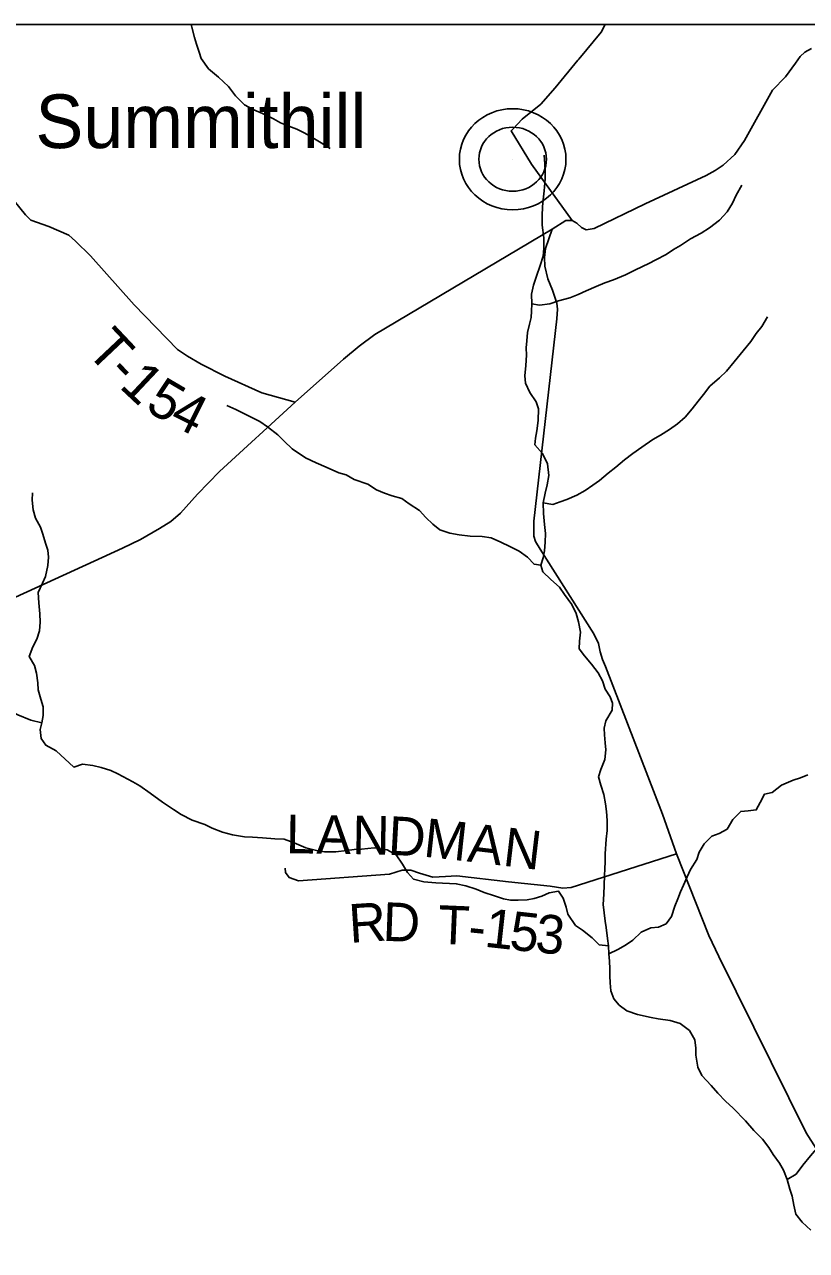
# Model space of a CAD drawing. Extents: x -139 to 835, y 0 to 440.
# Drawn here: x 206.1 to 242.7, y 344.1 to 401.5 of the extents above; entities that cross this region are included whole.
import ezdxf

# ---------------------------------------------------------------- set-up
doc = ezdxf.new("R2010")
doc.units = 0
for name, color, linetype in [('GM_X_County_Road', 7, 'Continuous'), ('GM_X_County_Text', 7, 'Continuous'), ('GM_X_Minor_River', 7, 'Continuous'), ('GM_X_State_Route', 7, 'Continuous'), ('GM_X_Township_Road', 7, 'Continuous'), ('GM_X_Township_Road_Text', 7, 'Continuous'), ('GM_X_Unincorporated', 7, 'Continuous'), ('GM_X_Unincorporated_Location', 7, 'Continuous'), ('GM_X_Unincorporated_Text', 7, 'Continuous'), ('SH_Cut_Line', 7, 'Continuous')]:
    doc.layers.add(name, color=color, linetype=linetype)

msp = doc.modelspace()

# ---------------------------------------------------------------- linework, layer by layer
at = {"layer": 'GM_X_County_Road'}
msp.add_lwpolyline([(243.129, 348.918), (242.661, 349.639), (238.58, 357.897), (238.118, 358.871), (236.599, 362.688), (235.94, 364.547), (233.28, 371.463), (233.147, 371.78), (233.028, 372.144), (232.948, 372.532), (232.741, 372.982), (230.219, 376.952), (230.011, 377.306), (229.927, 377.549), (229.93, 378.249), (231.007, 387.712), (231.043, 388.169), (230.999, 388.46), (230.795, 389.055), (230.578, 389.59), (230.439, 390.184), (230.435, 390.594), (230.47, 391.004), (230.781, 391.915)], dxfattribs=at)
at = {"layer": 'GM_X_County_Text'}
msp.add_lwpolyline([(295.458, 319.381), (295.458, 401.486), (205.139, 401.486), (203.623, 399.152), (203.278, 397.973), (203.246, 397.371), (203.294, 397.153), (203.078, 396.689), (187.014, 361.689), (186.616, 361.275), (186.292, 360.95), (186.018, 360.334), (185.902, 359.821), (185.729, 359.048), (185.383, 358.364), (184.767, 357.384), (172.321, 330.669), (171.559, 329.033), (177.155, 328.576), (194.287, 327.176), (207.436, 326.102), (228.151, 324.569), (267.909, 321.538)], close=True, dxfattribs=at)
at = {"layer": 'GM_X_Minor_River'}
for points in [[(213.904, 401.486), (213.938, 401.357), (214.06, 400.886), (214.157, 400.56), (214.268, 400.197), (214.366, 399.895), (214.704, 399.421), (215.182, 399.019), (215.647, 398.58), (215.973, 398.155), (216.4, 397.729), (216.83, 397.496), (217.234, 397.323), (217.753, 397.077), (218.081, 396.893), (218.473, 396.732), (218.84, 396.584), (219.219, 396.411), (219.598, 396.191), (219.977, 395.946), (220.406, 395.688)], [(230.406, 395.372), (230.44, 394.974), (230.461, 394.588), (230.457, 394.263), (230.412, 393.709), (230.369, 393.287), (230.34, 392.962), (230.323, 392.54), (230.317, 392.107), (230.4, 391.515), (230.394, 391.009), (230.364, 390.648), (230.232, 390.215), (230.061, 389.711), (229.916, 389.29), (229.822, 388.881), (229.83, 388.423), (229.826, 388.086), (229.797, 387.785), (229.73, 387.472), (229.636, 387.087), (229.594, 386.69), (229.577, 386.365), (229.586, 386.015), (229.555, 385.533), (229.511, 385.052), (229.545, 384.714), (229.744, 384.278), (230.044, 383.841), (230.154, 383.515), (230.135, 382.96), (230.066, 382.479), (230.011, 382.13), (229.982, 381.829), (230.334, 381.428), (230.569, 380.931), (230.627, 380.388), (230.558, 379.955), (230.465, 379.57), (230.37, 379.113), (230.377, 378.607), (230.435, 378.1), (230.468, 377.678), (230.463, 377.268), (230.421, 376.871), (230.366, 376.534), (230.26, 376.198), (230.346, 375.883), (230.723, 375.53), (231.125, 375.165), (231.363, 374.825), (231.713, 374.351), (231.912, 373.939), (232.022, 373.541), (232.118, 373.07), (232.062, 372.648), (232.045, 372.287), (232.296, 371.959), (232.622, 371.57), (232.935, 371.157), (233.147, 370.794), (233.269, 370.395), (233.494, 370.043), (233.605, 369.74), (233.588, 369.415), (233.29, 368.912), (233.223, 368.575), (233.232, 368.262), (233.266, 367.888), (233.3, 367.562), (233.257, 367.105), (233.06, 366.637), (232.955, 366.3), (233.065, 365.913), (233.2, 365.466), (233.284, 365.031), (233.33, 364.669), (233.364, 364.259), (233.358, 363.789), (233.315, 363.38), (233.269, 362.694), (233.265, 362.32), (233.248, 361.995), (233.232, 361.682), (233.214, 361.236), (233.197, 360.814), (233.178, 360.332), (233.212, 359.934), (233.271, 359.548), (233.318, 359.246), (233.376, 358.74), (233.423, 358.39), (233.444, 358.016), (233.465, 357.678), (233.487, 357.317), (233.483, 356.991), (233.492, 356.666), (233.538, 356.292), (233.674, 355.917), (233.925, 355.613), (234.278, 355.356)], [(229.83, 388.423), (230.198, 388.359), (230.682, 388.427), (231.09, 388.567), (231.613, 388.695), (232.009, 388.86), (232.379, 389.025), (232.852, 389.237), (233.248, 389.402), (233.656, 389.542), (234.218, 389.778), (234.691, 390.014), (235.305, 390.309), (235.637, 390.475), (236.111, 390.723), (236.456, 390.961), (236.789, 391.15), (237.263, 391.459), (237.762, 391.731), (238.146, 391.981), (238.621, 392.338), (238.969, 392.732), (239.215, 393.127), (239.397, 393.499), (239.657, 393.978)], [(230.37, 379.113), (230.814, 379.036), (231.159, 379.154), (231.478, 379.271), (231.938, 379.471), (232.335, 379.696), (232.681, 379.934), (233.001, 380.16), (233.412, 380.493), (233.758, 380.779), (234.169, 381.124), (234.566, 381.422), (234.977, 381.719), (235.502, 382.075), (235.86, 382.277), (236.27, 382.538), (236.642, 382.811), (237.001, 383.121), (237.336, 383.503), (237.62, 383.862), (237.865, 384.173), (238.162, 384.568), (238.611, 384.961), (238.933, 385.271), (239.294, 385.702), (239.719, 386.216), (240.08, 386.658), (240.326, 387.041), (240.597, 387.364), (240.856, 387.808)], [(230.26, 376.198), (229.943, 376.237), (229.629, 376.565), (229.238, 376.846), (228.809, 377.068), (228.379, 377.277), (227.936, 377.474), (227.517, 377.539), (226.958, 377.556), (226.438, 377.61), (226.007, 377.698), (225.538, 377.847), (225.198, 378.116), (224.884, 378.433), (224.582, 378.749), (224.09, 379.067), (223.75, 379.312), (223.306, 379.436), (222.939, 379.561), (222.572, 379.721), (222.169, 379.99), (221.523, 380.201), (221.157, 380.422), (220.815, 380.522), (220.22, 380.781), (219.752, 380.978), (219.247, 381.224), (218.629, 381.64), (218.251, 381.994), (217.95, 382.298), (217.471, 382.664), (217.118, 382.921), (216.335, 383.302), (215.993, 383.475), (215.576, 383.671)], [(206.474, 379.586), (206.47, 379.237), (206.515, 378.79), (206.624, 378.391), (206.847, 377.979), (206.957, 377.64), (207.091, 377.228), (207.201, 376.901), (207.222, 376.564), (207.192, 376.178), (207.084, 375.673), (206.941, 375.349), (206.746, 374.917), (206.778, 374.434), (206.822, 373.915), (206.842, 373.529), (206.799, 373.12), (206.681, 372.735), (206.499, 372.376), (206.328, 371.932), (206.564, 371.507), (206.673, 371.144), (206.731, 370.697), (206.74, 370.372), (206.861, 369.936), (206.983, 369.573), (206.978, 369.163), (206.911, 368.826), (206.844, 368.514), (206.876, 368.091), (207.101, 367.775), (207.579, 367.505)], [(206.911, 368.826), (206.405, 368.941), (205.788, 369.201), (205.435, 369.361), (205.046, 369.679), (204.684, 370.093), (204.256, 370.339), (203.803, 370.585), (203.286, 370.784), (202.934, 371.078), (202.635, 371.431), (202.398, 371.747), (202.06, 372.124), (201.595, 372.431), (201.081, 372.822), (200.589, 373.057), (200.135, 373.195), (199.781, 373.247), (199.426, 373.275), (198.958, 373.329)], [(233.423, 358.39), (232.979, 358.442), (232.652, 358.771), (232.198, 359.125), (231.87, 359.345), (231.521, 359.879), (231.448, 360.205), (231.3, 360.616), (231.088, 360.944), (230.642, 360.864), (230.297, 360.71), (229.94, 360.606), (229.609, 360.536), (229.189, 360.529), (228.833, 360.532), (228.503, 360.584), (228.086, 360.732), (227.604, 360.882), (227.225, 361.042), (226.744, 361.204), (226.3, 361.292), (225.347, 361.338), (224.788, 361.392), (224.294, 361.517), (224.018, 361.821), (223.793, 362.209), (223.493, 362.646), (223.064, 362.879), (222.455, 362.982), (221.87, 362.915), (221.526, 362.894), (221.182, 362.85), (220.66, 362.783), (220.139, 362.788), (219.759, 362.852), (219.264, 362.977), (218.72, 363.212), (218.252, 363.373), (217.82, 363.401), (217.236, 363.443), (216.766, 363.472), (216.397, 363.488), (215.827, 363.59), (215.358, 363.715), (214.889, 363.888), (214.536, 364.061), (213.953, 364.271), (213.435, 364.53), (213.069, 364.762), (212.552, 365.105), (211.985, 365.532), (211.506, 365.874), (211.177, 366.058), (210.47, 366.439), (210.141, 366.587), (209.685, 366.736), (209.305, 366.824), (208.81, 366.889), (208.414, 366.749), (207.579, 367.505)], [(233.444, 358.016), (233.853, 358.217), (234.224, 358.418), (234.557, 358.656), (234.943, 359.038), (235.403, 359.238), (235.759, 359.27), (236.117, 359.424), (236.375, 359.77), (236.52, 360.239), (236.664, 360.587), (236.782, 360.911), (236.926, 361.223), (237.108, 361.619), (237.252, 361.967), (237.55, 362.422), (237.668, 362.77), (237.889, 363.166), (238.249, 363.524), (238.594, 363.653), (238.977, 363.854), (239.237, 364.297), (239.61, 364.679), (239.953, 364.712), (240.335, 364.745), (240.517, 365.092), (240.725, 365.488), (241.082, 365.569), (241.518, 365.914), (242.055, 366.138), (242.399, 366.243), (242.744, 366.396)], [(241.775, 347.461), (242.198, 347.71), (242.508, 348.129), (242.869, 348.571), (243.255, 349.025), (243.54, 349.444), (243.76, 349.78), (244.329, 350.666), (244.537, 351.073), (244.847, 351.492), (245.222, 351.994), (245.505, 352.341), (245.93, 352.831), (246.227, 353.202), (246.602, 353.716), (246.938, 354.183), (247.272, 354.541), (247.593, 354.827), (247.978, 355.1), (248.426, 355.421), (248.836, 355.658)], [(234.278, 355.356), (234.784, 355.183), (235.418, 355.032), (235.748, 354.98), (236.306, 354.891), (236.775, 354.765), (237.203, 354.436), (237.453, 353.999), (237.499, 353.601), (237.508, 353.276), (237.603, 352.709), (237.789, 352.321), (238.229, 351.859), (238.542, 351.506), (238.894, 351.129), (239.246, 350.8), (239.824, 350.204), (240.213, 349.754), (240.628, 349.353), (240.916, 348.964), (241.128, 348.625), (241.416, 348.224), (241.602, 347.897), (241.775, 347.461), (241.91, 347.014), (242.008, 346.676), (242.092, 346.253), (242.189, 345.843), (242.477, 345.466), (242.892, 345.089)]]:
    msp.add_lwpolyline(points, dxfattribs=at)
at = {"layer": 'GM_X_State_Route'}
msp.add_lwpolyline([(205.689, 374.7), (209.356, 376.38), (210.687, 376.99), (211.523, 377.403), (212.424, 377.91), (212.953, 378.236), (213.403, 378.637), (214.196, 379.524), (215.219, 380.585), (218.772, 383.829), (221.029, 385.836), (221.76, 386.438), (222.492, 386.981), (230.781, 391.915), (231.432, 392.315), (231.714, 392.323), (231.943, 392.198), (232.163, 391.989), (232.384, 391.88), (232.745, 391.939), (235.134, 393.101), (237.991, 394.43), (238.405, 394.664), (238.784, 394.907), (239.326, 395.406), (239.789, 396.06), (241.097, 398.423), (241.694, 399.037), (242.168, 399.681), (242.39, 399.998), (242.611, 400.19), (242.91, 400.366)], dxfattribs=at)
at = {"layer": 'GM_X_Township_Road'}
for points in [[(231.99, 399.816), (232.031, 399.866), (233.079, 401.134), (233.265, 401.481), (233.265, 401.486)], [(231.714, 392.323), (229.826, 394.962), (228.868, 396.512), (228.958, 396.607), (229.389, 397.057), (230.257, 397.764), (230.922, 398.523), (231.99, 399.816)], [(218.772, 383.829), (217.199, 384.253), (215.472, 385.041), (214.36, 385.594), (213.725, 385.975), (213.253, 386.279), (211.239, 388.369), (209.193, 390.665), (208.492, 391.35), (208.171, 391.626), (207.245, 392.04), (206.403, 392.331), (206.158, 392.592), (204.805, 394.222), (204.136, 395.143)], [(218.298, 362.02), (218.307, 361.815), (218.48, 361.583), (218.922, 361.429), (223.178, 361.745), (223.767, 361.927), (224.174, 361.931), (224.578, 361.791), (225.197, 361.598), (225.796, 361.635), (226.331, 361.661), (228.742, 361.385), (230.697, 361.179), (231.292, 361.083), (231.675, 361.124), (236.599, 362.688)]]:
    msp.add_lwpolyline(points, dxfattribs=at)
at = {"layer": 'GM_X_Unincorporated'}
for major_axis in [(2.493, 0), (1.581, 0)]:
    msp.add_ellipse((228.938, 395.184), major_axis=major_axis, ratio=0.948307, dxfattribs=at)
at = {"layer": 'GM_X_Unincorporated_Location'}
msp.add_line((228.938, 395.184), (228.938, 395.184), dxfattribs=at)
at = {"layer": 'SH_Cut_Line'}
msp.add_lwpolyline([(295.458, 319.381), (295.458, 401.486), (67.578, 401.486), (67.578, 336.518), (92.493, 334.759), (105.67, 333.828), (158.444, 330.1), (160.688, 329.921), (171.559, 329.033), (177.155, 328.576), (194.287, 327.176), (207.436, 326.102), (228.151, 324.569), (267.909, 321.538)], close=True, dxfattribs=at)

# ---------------------------------------------------------------- texts
at = {"layer": 'GM_X_Township_Road_Text'}
for s, height, rotation, p in [('T', 1.878, 313.32068, (208.927, 386.178)), ('-', 1.877, 313.71913, (209.886, 385.161)), ('1', 1.872, 316.82564, (210.489, 384.535)), ('5', 1.847, 329.62443, (211.691, 383.477)), ('4', 1.839, 333.45644, (212.813, 382.825)), ('L', 1.806, 359.22373, (218.328, 362.725)), ('A', 1.806, 359.22485, (219.752, 362.706)), ('N', 1.806, 359.08277, (221.426, 362.683)), ('D', 1.806, 356.89069, (223.081, 362.657)), ('M', 1.808, 353.72307, (224.724, 362.569)), ('A', 1.808, 353.19603, (226.772, 362.343)), ('N', 1.808, 353.20253, (228.435, 362.145)), ('R', 1.806, 3.76585, (221.331, 358.527)), ('D', 1.806, 357.868, (222.837, 358.629)), ('T', 1.806, 357.6073, (225.412, 358.492)), ('1', 1.808, 353.65358, (227.576, 358.355)), ('5', 1.808, 353.68298, (228.742, 358.225)), ('3', 1.807, 354.9438, (229.955, 358.091)), ('-', 1.808, 354.11236, (226.803, 358.435))]:
    msp.add_text(s, height=height, rotation=rotation, dxfattribs=at).set_placement(p)
at = {"layer": 'GM_X_Unincorporated_Text'}
msp.add_text('Summithill', height=2.5099, rotation=0.00001, dxfattribs=at).set_placement((206.616, 395.706))

doc.saveas('drawing.dxf')
